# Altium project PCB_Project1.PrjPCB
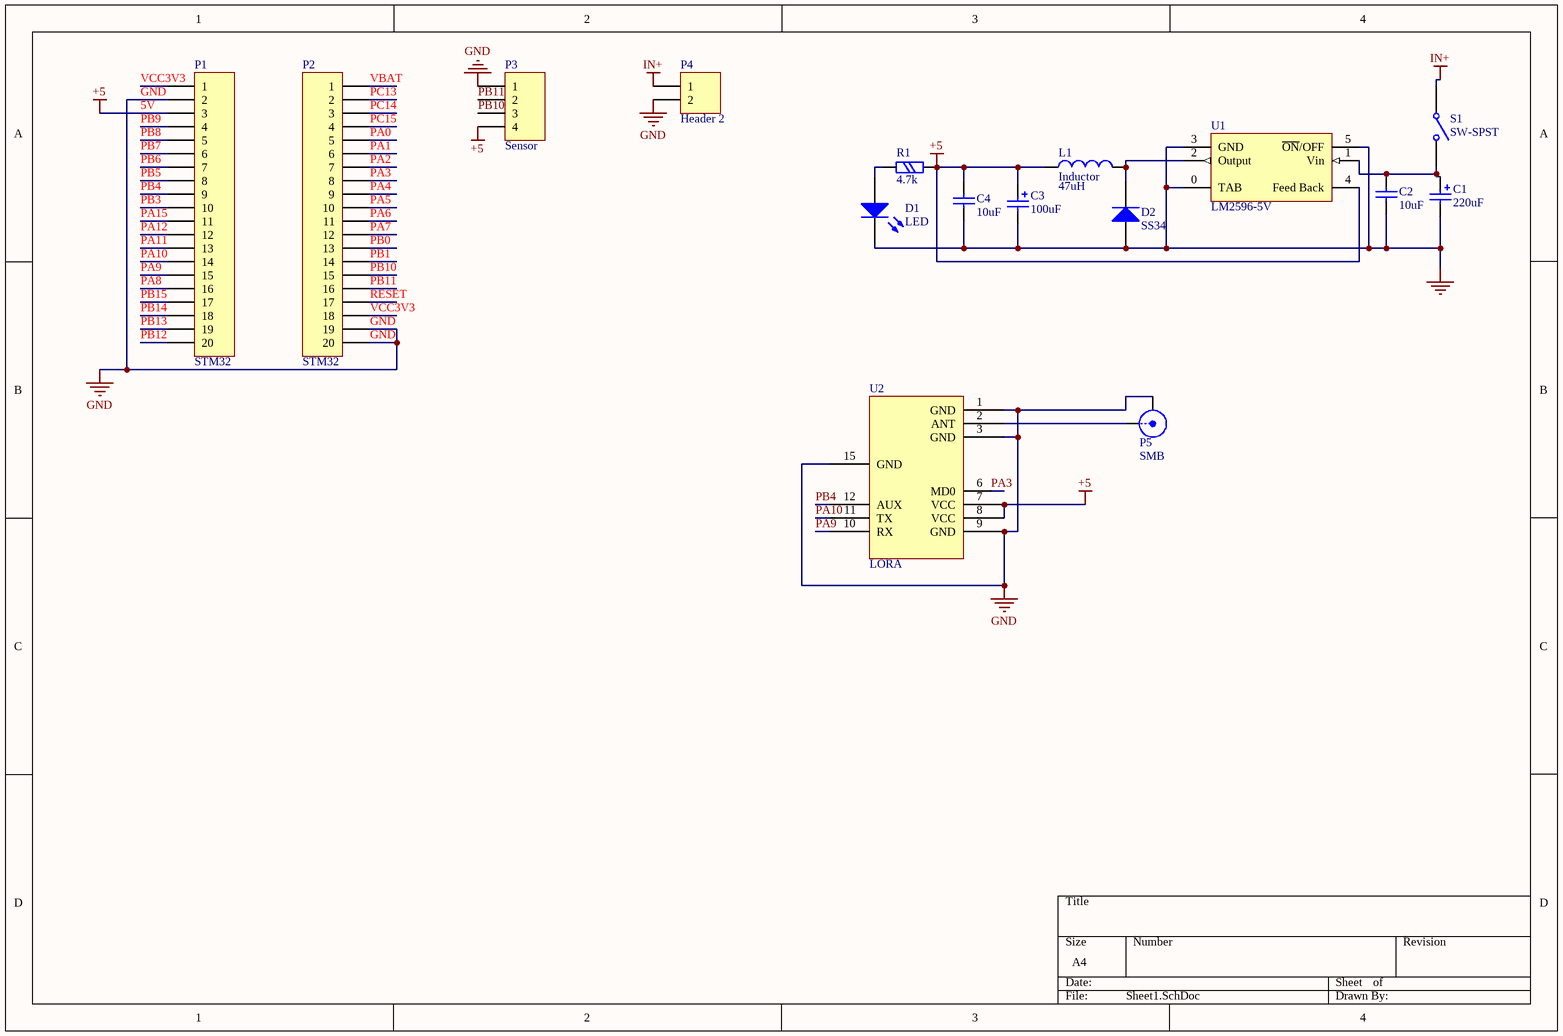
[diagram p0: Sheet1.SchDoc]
1 sheet, 16 parts. Net scope: global (net labels, ports and power ports of the same name join across sheets).
Board files: PCB1.PcbDoc, ATK-LORA-02（封装）.PcbDoc, logo.PcbDoc

## Sheet Sheet1.SchDoc
size A4

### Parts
C1  CAP1  [CAP+]  (value not drawn)
C2  CAP  [CAP]  (value not drawn)
C3  CAP1  [CAP+]  (value not drawn)
C4  CAP  [CAP]  (value not drawn)
D1  LED  [LED]
D2  SS34  [SS34]
L1  Inductor  value 47uH  [470]
P1  STM32  [HDR1X20]
P2  STM32  [HDR1X20]
P3  Sensor  [HDR1X4]
P4  Header 2  [HDR2]
P5  SMB  [SMA-KE]
R1  4.7k  [6-0805_M]
S1  SW-SPST  [SK-22D02]
U1  LM2596-5V  [LM2596S]
U2  LORA  [LORA]

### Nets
5V: C3.1 C4.1 L1.1 P1.3 P3.4 R1.1 U1.4(Feed_Back) U2.7(VCC) U2.8(VCC)  [also labelled +5]
GND: C1.2 C2.2 C3.2 C4.2 D1.2(K) D2.1(A) P1.2 P2.19 P2.20 P3.1 P4.2 P5.2(Y) U1.0(TAB) U1.3(GND) U1.5(~{ON}/OFF) U2.1(GND) U2.3(GND) U2.9(GND) U2.15(GND)
IN+: P4.1 S1.1(COMMON)
PA0: P2.5
PA1: P2.6
PA2: P2.7
PA3: P2.8 U2.6(MD0)
PA4: P2.9
PA5: P2.10
PA6: P2.11
PA7: P2.12
PA8: P1.16
PA9: P1.15 U2.10(RX)
PA10: P1.14 U2.11(TX)
PA11: P1.13
PA12: P1.12
PA15: P1.11
PB0: P2.13
PB1: P2.14
PB3: P1.10
PB4: P1.9 U2.12(AUX)
PB5: P1.8
PB6: P1.7
PB7: P1.6
PB8: P1.5
PB9: P1.4
PB10: P2.15 P3.3
PB11: P2.16 P3.2
PB12: P1.20
PB13: P1.19
PB14: P1.18
PB15: P1.17
PC13: P2.2
PC14: P2.3
PC15: P2.4
RESET: P2.17
VBAT: P2.1
VCC3V3: P1.1 P2.18
NetC1_1: C1.1 C2.1 S1.2(NO) U1.1(Vin)
NetD1_1: D1.1(A) R1.2
NetD2_2: D2.2(K) L1.2 U1.2(Output)
NetP5_1: P5.1(X) U2.2(ANT)

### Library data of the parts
D2 = DIODE
L1 = Inductor: Code_IEC: 1005
P1 P2 = Header 20: Header, 20-Pin
P3 = Header 4: Header, 4-Pin
P4 = Header 2: Header, 2-Pin
P5 = SMB: SMB Straight Connector
R1 = RES
S1 = SW-SPST: Single-Pole, Single-Throw Switch
U1 = LM2596S
U2 = Component_1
